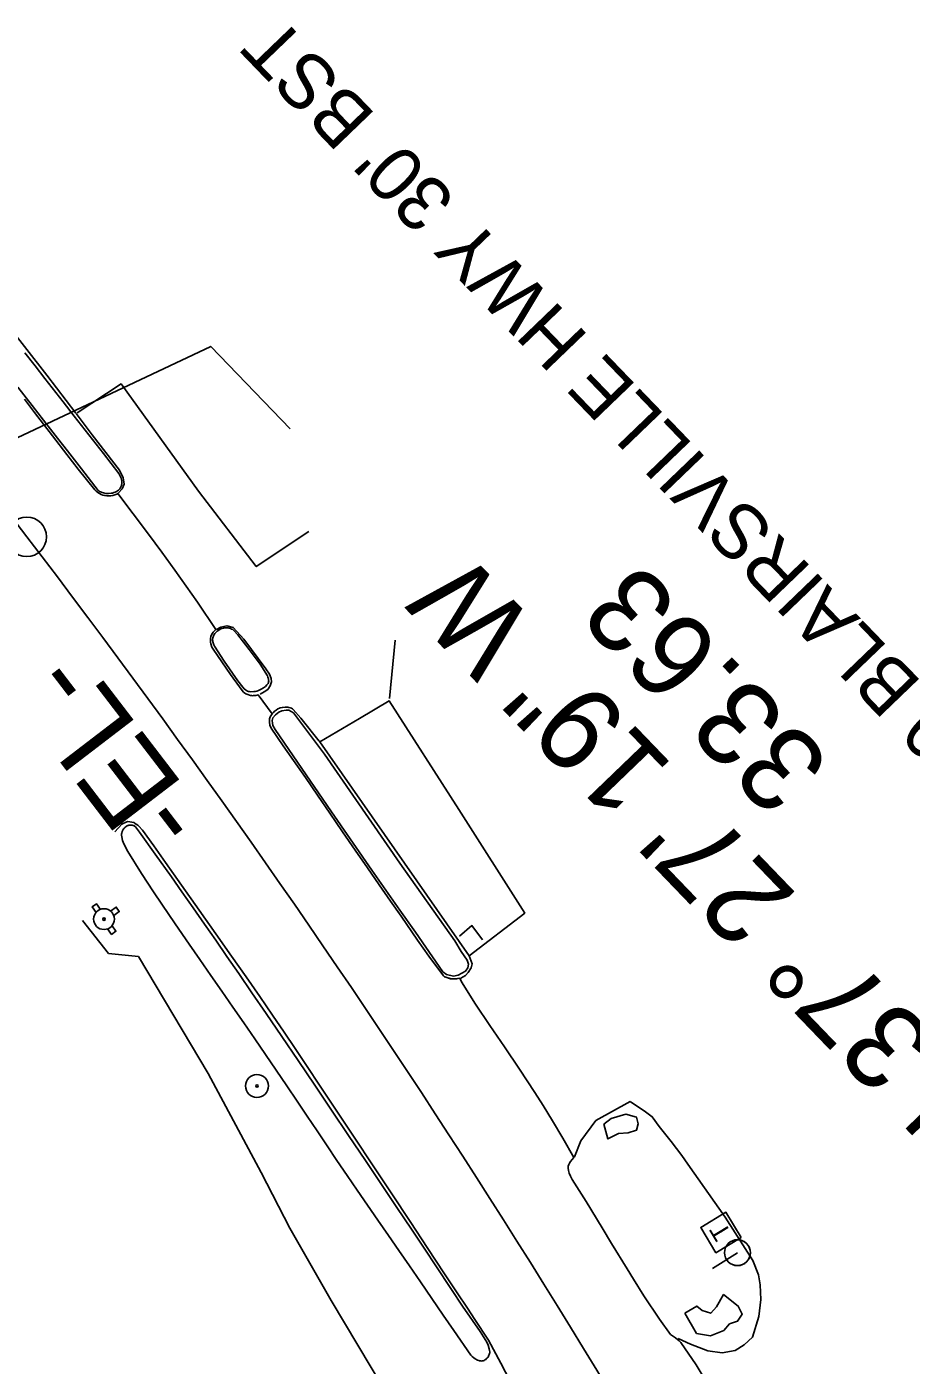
# Model space of a CAD drawing. Extents: x 471894 to 476235, y 503501 to 507878.
# Drawn here: x 474137 to 474304.9, y 505467.5 to 505721.6 of the extents above; entities that cross this region are included whole.
import ezdxf

# ---------------------------------------------------------------- set-up
doc = ezdxf.new("R2010")
doc.units = 0
for name, color, linetype in [('CTL Secondary Horizontal and Vertical Leader', 7, 'Continuous'), ('Exist Horizontal Alignment', 7, 'Continuous'), ('Exist Horizontal Alignment Direction Label', 7, 'Continuous'), ('Exist Other Culture Area Outline', 7, 'Continuous'), ('Exist Roads Curbs', 7, 'Continuous'), ('Exist Roads EOP', 7, 'Continuous'), ('Exist Roads EOP Other', 7, 'Continuous'), ('Exist Roads EOP Text', 7, 'Continuous'), ('Exist Roads Soil', 7, 'Continuous'), ('Exist Utilities Other Located Object CELL', 7, 'Continuous'), ('Exist Utilities Other Pole CELL', 7, 'Continuous'), ('Exist Utilities Power Pole CELL', 7, 'Continuous'), ('Exist Utilities Telephone Pedestal CELL', 7, 'Continuous'), ('Exist Utilities Water Fire Hydrant CELL', 7, 'Continuous')]:
    doc.layers.add(name, color=color, linetype=linetype)

msp = doc.modelspace()

# ---------------------------------------------------------------- linework, layer by layer
at = {"layer": 'CTL Secondary Horizontal and Vertical Leader'}
msp.add_lwpolyline([(474127.3, 505639.88), (474171.9, 505660.95), (474186.96, 505645.3)], dxfattribs=at)
at = {"layer": 'Exist Horizontal Alignment'}
msp.add_line((474136.95, 505624.79), (474116.5, 505651.49), dxfattribs=at)
msp.add_circle((474136.95, 505624.79), 3.75, dxfattribs=at)
msp.add_arc((472721.75, 504540.63), 1782.75, 27.59346, 37.45515, dxfattribs=at)
at = {"layer": 'Exist Other Culture Area Outline'}
for points in [[(474246.53, 505513.3), (474247.3, 505510.47), (474249.32, 505511.49), (474251.15, 505511.64), (474252.72, 505512.12), (474253.04, 505513.35), (474252.7, 505514.61), (474250.71, 505515.2), (474247.9, 505514.34), (474246.53, 505513.3)], [(474261.91, 505477.38), (474264.14, 505473.55), (474266.77, 505473.11), (474269.29, 505474.13), (474270.4, 505475.36), (474271.91, 505475.85), (474272.8, 505477.19), (474272.04, 505478.74), (474269.27, 505480.91), (474267.9, 505478.58), (474266.83, 505477.38), (474265.22, 505477.91), (474264.21, 505478.75), (474261.91, 505477.38)]]:
    msp.add_lwpolyline(points, dxfattribs=at)
at = {"layer": 'Exist Roads Curbs'}
msp.add_lwpolyline([(474135.27, 505653.2), (474137.99, 505649.7), (474140.15, 505646.93), (474142.79, 505643.54), (474144.68, 505641.11), (474147.32, 505637.7), (474150.54, 505633.6), (474150.66, 505633.5), (474150.79, 505633.41), (474150.95, 505633.32), (474151.12, 505633.24), (474151.3, 505633.17), (474151.51, 505633.12), (474151.96, 505633.04), (474152.46, 505633.01), (474152.97, 505633.06), (474153.23, 505633.1), (474153.48, 505633.18), (474153.72, 505633.27), (474153.96, 505633.4), (474154.35, 505633.65), (474154.49, 505633.78), (474154.6, 505633.9), (474154.76, 505634.14), (474154.82, 505634.27), (474154.88, 505634.39), (474154.93, 505634.53), (474154.96, 505634.66), (474154.99, 505634.8), (474155, 505634.95), (474155.01, 505635.09), (474155, 505635.23), (474154.99, 505635.37), (474154.93, 505635.64), (474154.85, 505635.91), (474154.61, 505636.45), (474154.42, 505636.8), (474151.51, 505640.63), (474148.76, 505644.13), (474145.96, 505647.69), (474143.85, 505650.4), (474140.4, 505654.84), (474138.52, 505657.25), (474136.61, 505659.73)], dxfattribs=at)
for points in [[(474182.89, 505597.45), (474182.88, 505597.63), (474182.85, 505597.8), (474182.81, 505597.98), (474182.75, 505598.17), (474182.64, 505598.41), (474181.25, 505600.61), (474179.19, 505603.42), (474177.04, 505606.15), (474176.29, 505606.97), (474176.05, 505607.16), (474175.85, 505607.27), (474175.64, 505607.37), (474175.41, 505607.44), (474175.17, 505607.49), (474174.93, 505607.52), (474174.71, 505607.53), (474174.5, 505607.52), (474174.31, 505607.47), (474173.98, 505607.36), (474173.69, 505607.24), (474173.41, 505607.07), (474173.1, 505606.85), (474172.94, 505606.71), (474172.8, 505606.57), (474172.67, 505606.42), (474172.56, 505606.27), (474172.47, 505606.11), (474172.39, 505605.95), (474172.33, 505605.78), (474172.29, 505605.62), (474172.25, 505605.29), (474172.25, 505605.14), (474172.26, 505605), (474172.28, 505604.85), (474172.38, 505604.5), (474172.46, 505604.3), (474172.6, 505604), (474174.41, 505601.2), (474177.06, 505597.43), (474177.98, 505596.22), (474178.26, 505595.91), (474178.47, 505595.72), (474178.68, 505595.58), (474178.88, 505595.47), (474179.07, 505595.42), (474179.27, 505595.39), (474179.5, 505595.38), (474180.06, 505595.4), (474180.36, 505595.45), (474180.65, 505595.51), (474180.94, 505595.6), (474181.47, 505595.84), (474181.91, 505596.1), (474182.26, 505596.38), (474182.54, 505596.67), (474182.66, 505596.81), (474182.76, 505596.96), (474182.84, 505597.12), (474182.88, 505597.28)], [(474187.55, 505583.22), (474194.84, 505572.59), (474202.48, 505561.49), (474207.77, 505553.93), (474210.79, 505549.74), (474215.97, 505542.21), (474216.67, 505541.69), (474217.98, 505541.4), (474218.88, 505541.57), (474220.23, 505542.34), (474220.67, 505542.97), (474220.8, 505543.67), (474220.58, 505544.44), (474219.46, 505546.08), (474218.22, 505548.1), (474207.82, 505562.85), (474193.5, 505583.52), (474187.62, 505591.34), (474186.73, 505591.85), (474186.21, 505591.88), (474185.36, 505591.78), (474184.82, 505591.5), (474184.16, 505590.98), (474183.68, 505590.39), (474183.57, 505589.91), (474183.58, 505589.42), (474183.66, 505588.97), (474184.14, 505588.18)], [(474156.15, 505565.05), (474158.76, 505560.88), (474161.04, 505557.39), (474164.03, 505552.91), (474165.8, 505550.31), (474167.76, 505547.48), (474169.82, 505544.52), (474171.89, 505541.53), (474173.97, 505538.54), (474176.07, 505535.52), (474178.16, 505532.5), (474180.23, 505529.5), (474182.28, 505526.5), (474184.31, 505523.52), (474186.32, 505520.56), (474188.28, 505517.66), (474190.2, 505514.8), (474192.08, 505511.98), (474193.96, 505509.18), (474195.85, 505506.37), (474197.77, 505503.55), (474199.71, 505500.73), (474201.67, 505497.88), (474203.64, 505495.03), (474205.62, 505492.17), (474207.62, 505489.29), (474209.64, 505486.36), (474211.72, 505483.33), (474213.86, 505480.21), (474216.04, 505476.99), (474218.01, 505474.09), (474221.28, 505469.43), (474221.55, 505469.15), (474221.81, 505468.93), (474222.08, 505468.75), (474222.56, 505468.49), (474222.76, 505468.41), (474222.94, 505468.35), (474223.11, 505468.32), (474223.28, 505468.31), (474223.45, 505468.32), (474223.62, 505468.36), (474223.79, 505468.43), (474223.95, 505468.52), (474224.11, 505468.62), (474224.26, 505468.76), (474224.4, 505468.9), (474224.53, 505469.06), (474224.63, 505469.22), (474224.71, 505469.39), (474224.78, 505469.57), (474224.83, 505469.73), (474224.85, 505469.89), (474224.86, 505470.03), (474224.84, 505470.32), (474224.78, 505470.62), (474224.54, 505471.33), (474224.29, 505471.86), (474223.01, 505473.93), (474219.71, 505478.73), (474217.62, 505481.86), (474214.62, 505486.4), (474212.51, 505489.56), (474210, 505493.32), (474207.22, 505497.48), (474204.31, 505501.83), (474201.25, 505506.39), (474198.05, 505511.15), (474194.81, 505515.96), (474191.62, 505520.69), (474188.48, 505525.34), (474185.38, 505529.91), (474182.43, 505534.26), (474179.71, 505538.24), (474177.22, 505541.86), (474174.97, 505545.12), (474172.84, 505548.2), (474170.7, 505551.26), (474168.56, 505554.33), (474166.41, 505557.38), (474164.41, 505560.22), (474161.33, 505564.56), (474158.35, 505568.7), (474157.81, 505569.48), (474157.61, 505569.7), (474157.51, 505569.79), (474157.42, 505569.85), (474157.33, 505569.9), (474157.15, 505569.98), (474156.94, 505570.03), (474156.83, 505570.05), (474156.71, 505570.06), (474156.59, 505570.06), (474156.47, 505570.05), (474156.34, 505570.04), (474156.22, 505570.01), (474156.11, 505569.97), (474156.01, 505569.93), (474155.91, 505569.87), (474155.81, 505569.81), (474155.61, 505569.64), (474155.51, 505569.54), (474155.42, 505569.44), (474155.34, 505569.32), (474155.19, 505569.07), (474155.08, 505568.81), (474155, 505568.55), (474154.97, 505568.42), (474154.96, 505568.29), (474154.95, 505568.17), (474154.99, 505567.85), (474155.15, 505567.13), (474155.39, 505566.49)]]:
    msp.add_lwpolyline(points, close=True, dxfattribs=at)
at = {"layer": 'Exist Roads EOP'}
for points in [[(474136.5, 505650.9), (474138.44, 505648.4), (474141.81, 505643.99), (474144.57, 505640.4), (474146.73, 505637.64), (474149.88, 505633.73), (474150.15, 505633.45), (474150.42, 505633.23), (474150.74, 505633), (474151.07, 505632.83), (474151.41, 505632.7), (474151.76, 505632.61), (474152.13, 505632.56), (474152.5, 505632.55), (474152.89, 505632.58), (474153.27, 505632.64), (474153.66, 505632.74), (474153.85, 505632.82), (474154.05, 505632.91), (474154.24, 505633.03), (474157.15, 505629.17), (474160.05, 505625.31), (474162.57, 505621.87), (474165.09, 505618.43), (474169.36, 505612.38), (474172.85, 505607.16), (474172.35, 505606.69), (474172.19, 505606.5), (474172.04, 505606.19), (474171.93, 505605.87), (474171.86, 505605.51), (474171.82, 505605.16), (474171.84, 505604.81), (474171.91, 505604.46), (474172.1, 505603.84), (474172.33, 505603.44), (474175.63, 505598.65), (474177.86, 505595.61), (474178.13, 505595.32), (474178.36, 505595.11), (474178.55, 505594.98), (474178.91, 505594.82), (474179.27, 505594.7), (474179.45, 505594.65), (474179.64, 505594.63), (474179.83, 505594.62), (474180.03, 505594.63), (474180.44, 505594.69), (474180.86, 505594.81), (474183.56, 505591.18), (474183.27, 505590.77), (474183.18, 505590.59), (474183.07, 505590.26), (474183.03, 505589.93), (474183.02, 505589.58), (474183.08, 505589.03), (474183.38, 505588.47), (474185.64, 505585.1), (474187.6, 505582.29), (474189.85, 505579.07), (474192.16, 505575.74), (474194.52, 505572.32), (474196.93, 505568.79), (474199.33, 505565.29), (474201.65, 505561.92), (474203.88, 505558.69), (474206.03, 505555.59), (474208.01, 505552.75), (474211.17, 505548.23), (474213.32, 505545.18), (474216.08, 505541.42), (474216.3, 505541.28), (474217.15, 505540.98), (474217.43, 505540.92), (474217.71, 505540.89), (474218.29, 505540.9), (474219.15, 505540.99), (474219.48, 505540.33), (474222.17, 505536.04), (474224.87, 505532.01), (474227.67, 505527.93), (474230.53, 505523.71), (474233.44, 505519.27), (474235, 505516.79), (474236.76, 505513.91), (474238.71, 505510.63), (474240.85, 505506.95), (474240.21, 505506.2), (474240, 505505.88), (474239.85, 505505.61), (474239.78, 505505.31), (474239.77, 505504.95), (474239.83, 505504.5), (474239.96, 505503.98), (474240.18, 505503.4), (474240.49, 505502.76), (474243.16, 505498.57), (474246.21, 505493.57), (474247.97, 505490.65), (474250.94, 505485.79), (474252.15, 505483.83), (474254.13, 505480.69), (474257.1, 505476.26), (474259.21, 505473.35), (474260.13, 505472.72), (474260.82, 505472.15), (474261.13, 505471.83), (474264.05, 505467.56), (474265.59, 505465.04)], [(474229.65, 505462.8), (474226.94, 505467.93), (474224.64, 505472.3), (474222.05, 505476.21), (474220.62, 505478.32), (474218.65, 505481.27), (474216.14, 505485.06), (474213.09, 505489.69), (474209.72, 505494.8), (474206.28, 505500.02), (474202.75, 505505.34), (474199.14, 505510.78), (474195.7, 505515.95), (474192.67, 505520.49), (474190.07, 505524.39), (474187.89, 505527.66), (474185.83, 505530.72), (474183.6, 505534), (474181.19, 505537.5), (474178.61, 505541.23), (474175.84, 505545.19), (474172.87, 505549.42), (474169.71, 505553.91), (474166.36, 505558.65), (474163.31, 505562.97), (474161.05, 505566.15), (474158.9, 505569.11), (474158.26, 505569.86), (474158.01, 505570.06), (474157.75, 505570.23), (474157.47, 505570.38), (474157.32, 505570.52), (474156.07, 505570.73), (474155, 505570.23), (474153.7, 505568.77)]]:
    msp.add_lwpolyline(points, dxfattribs=at)
at = {"layer": 'Exist Roads EOP Other'}
for points in [[(474146.51, 505648.3), (474154.87, 505653.81), (474169.53, 505633.44), (474180.51, 505619.14), (474190.54, 505625.79)], [(474154.36, 505633.15), (474155.08, 505633.88), (474155.44, 505634.76), (474155.25, 505635.99), (474154.54, 505637.45), (474149.36, 505644.17), (474146.31, 505648.17)], [(474181.25, 505594.94), (474182.06, 505595.34), (474182.75, 505595.82), (474183.16, 505596.49), (474183.41, 505597.23), (474183.37, 505597.9), (474183.07, 505598.74), (474182.35, 505599.75), (474178.15, 505605.38), (474176.14, 505607.54), (474174.92, 505607.87), (474173.82, 505607.65), (474172.95, 505607.21)], [(474205.8, 505594.07), (474206.9, 505605.19)], [(474183.66, 505591.32), (474183.79, 505591.46), (474183.93, 505591.6), (474184.28, 505591.87), (474184.63, 505592.1), (474184.93, 505592.26), (474185.08, 505592.32), (474185.48, 505592.41), (474186, 505592.46), (474186.25, 505592.47), (474186.5, 505592.45), (474186.74, 505592.41), (474186.97, 505592.35), (474187.19, 505592.27), (474187.38, 505592.16), (474187.56, 505592.03), (474188.98, 505590.35), (474192.47, 505586.01)], [(474223.46, 505548.26), (474221.49, 505550.97), (474219.13, 505548.99)]]:
    msp.add_lwpolyline(points, dxfattribs=at)
msp.add_lwpolyline([(474200.16, 505590.27), (474192.58, 505585.88), (474220.97, 505545.24), (474231.51, 505553.36), (474218.99, 505573.01), (474205.76, 505593.66)], close=True, dxfattribs=at)
at = {"layer": 'Exist Roads Soil'}
msp.add_line((474244.99, 505513.96), (474251.51, 505517.58), dxfattribs=at)
for points in [[(474146.25, 505648.25), (474140.76, 505655.46), (474119.23, 505683), (474107.74, 505697.85), (474107.74, 505697.85), (474097.02, 505711.2), (474096.21, 505711.62), (474095.17, 505711.89), (474094.56, 505711.77), (474093.79, 505711.47)], [(474147.52, 505551.93), (474152.49, 505545.7), (474158.14, 505545.1), (474171.39, 505522.9), (474181.45, 505504.07), (474186.89, 505493.52), (474194.75, 505479.78), (474204.89, 505462.83), (474197.95, 505457.72), (474197.58, 505455.59), (474200.37, 505452.99), (474206.26, 505450.93), (474213.01, 505451.16), (474218.25, 505454.41), (474218.31, 505454.46)], [(474219.38, 505541.02), (474220.25, 505541.49), (474220.76, 505542.04), (474221.34, 505542.97), (474221.53, 505543.71), (474220.97, 505545.24)], [(474216.35, 505541.26), (474217.42, 505540.87), (474218.58, 505540.9), (474219.15, 505540.99)], [(474274.73, 505472.84), (474275.96, 505476.75), (474276.31, 505479.97), (474276.19, 505482.76), (474275.88, 505484.69), (474274.84, 505487.42), (474269.53, 505495.63), (474262.48, 505505.7), (474261.33, 505507.33), (474259.32, 505509.97), (474257.05, 505512.81), (474255.73, 505514.7), (474254.41, 505515.65), (474251.51, 505517.58)], [(474240.97, 505507.07), (474242.16, 505510.09), (474244.99, 505513.96)], [(474260.62, 505472.57), (474263, 505471.48), (474266.25, 505470.24), (474268.96, 505469.89), (474271.44, 505470.33), (474273.16, 505471.41), (474274.73, 505472.84)]]:
    msp.add_lwpolyline(points, dxfattribs=at)
at = {"layer": 'Exist Utilities Other Located Object CELL'}
for radius in [2.18, 0.24]:
    msp.add_circle((474180.66, 505520.53), radius, dxfattribs=at)
at = {"layer": 'Exist Utilities Other Pole CELL'}
msp.add_circle((474271.89, 505488.88), 2.46, dxfattribs=at)
at = {"layer": 'Exist Utilities Power Pole CELL'}
for q in [(474267.15, 505485.86), (474271.89, 505488.88)]:
    msp.add_line((474271.89, 505488.88), q, dxfattribs=at)
msp.add_circle((474271.89, 505488.88), 2.45, dxfattribs=at)
at = {"layer": 'Exist Utilities Telephone Pedestal CELL'}
msp.add_line((474268.78, 505492.63), (474268.78, 505492.63), dxfattribs=at)
msp.add_lwpolyline([(474272.61, 505491.76), (474269.71, 505496.55), (474264.93, 505493.66), (474267.82, 505488.87), (474272.61, 505491.76)], dxfattribs=at)
at = {"layer": 'Exist Utilities Water Fire Hydrant CELL'}
msp.add_line((474151.62, 505552.21), (474151.62, 505552.21), dxfattribs=at)
for points in [[(474150.93, 505554.06), (474150.18, 505555.11), (474149.34, 505554.52), (474150.1, 505553.45)], [(474153.47, 505552.9), (474154.52, 505553.64), (474153.93, 505554.48), (474152.88, 505553.73)], [(474153.14, 505550.95), (474153.89, 505549.9), (474153.05, 505549.3), (474152.29, 505550.37)]]:
    msp.add_lwpolyline(points, dxfattribs=at)
for radius in [1.98, 0.243]:
    msp.add_circle((474151.62, 505552.21), radius, dxfattribs=at)

# ---------------------------------------------------------------- texts
at = {"layer": 'Exist Horizontal Alignment Direction Label'}
for s, rotation, p in [('N 37%%d 27\' 19" W', 133.8986, (474324.85, 505513.67)), ('33.63', 133.8986, (474290.11, 505581.9)), ('-EL-', 127.4552, (474171.3, 505571.69))]:
    msp.add_text(s, height=16, rotation=rotation, dxfattribs=at).set_placement(p)
at = {"layer": 'Exist Roads EOP Text'}
msp.add_text("US19/129 BLAIRSVILLE HWY 30' BST", height=10.4, rotation=133.8986, dxfattribs=at).set_placement((474352.72, 505549.64))
at = {"layer": 'Exist Utilities Telephone Pedestal CELL'}
msp.add_text('T', height=3.42, rotation=121.14, dxfattribs=at).set_placement((474270.83, 505492.55))

doc.saveas('drawing.dxf')
